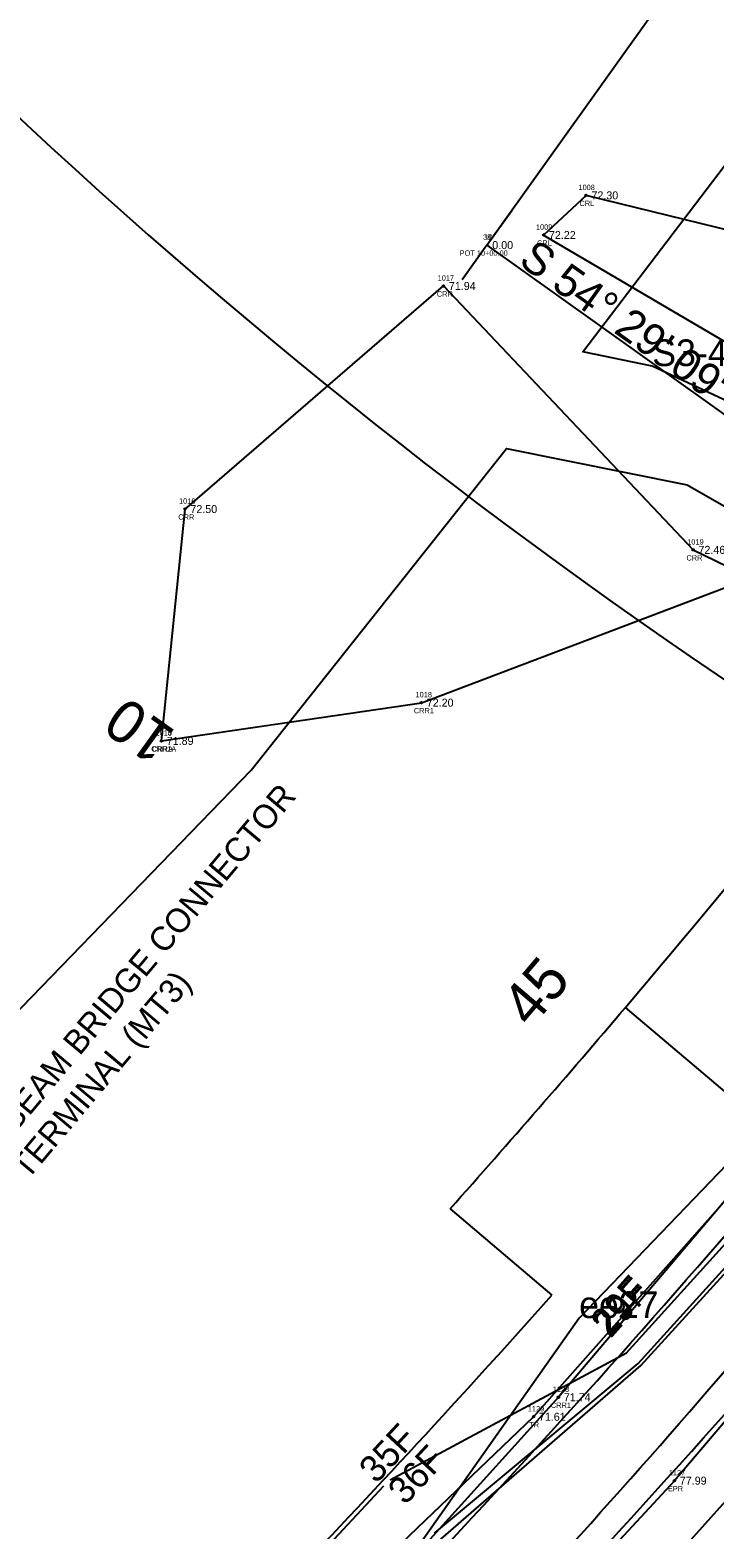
# Model space of a CAD drawing. Extents: x 2500794 to 2511032, y 910653 to 917533.
# Drawn here: x 2505570 to 2505698.2, y 913378 to 913659 of the extents above; entities that cross this region are included whole.
import ezdxf

# ---------------------------------------------------------------- set-up
doc = ezdxf.new("R2010")
doc.units = 0
for name, color, linetype in [('Default', 7, 'Continuous'), ('RD_EX_H2O', 7, 'Continuous'), ('RD_EX_H2O_txCode', 7, 'Continuous'), ('RD_EX_H2O_WetLd', 7, 'Continuous'), ('RD_EX_Road', 7, 'Continuous'), ('RD_EX_Road_txCode', 7, 'Continuous'), ('RD_EX_RW', 7, 'Continuous'), ('RD_EX_TX_H2O_ELEV', 7, 'Continuous'), ('RD_EX_TX_Road_ELEV', 7, 'Continuous'), ('RD_EX_TX_VEG_ELEV', 7, 'Continuous'), ('RD_EX_VEG', 7, 'Continuous'), ('RD_EX_VEG_txCode', 7, 'Continuous'), ('RD_EX_Wall', 7, 'Continuous'), ('RD_HC_Cl', 7, 'Continuous'), ('RD_HC_Data', 7, 'Continuous'), ('RD_HC_Data_Tic', 7, 'Continuous'), ('RD_HC_Survey_ELEV', 7, 'Continuous'), ('RD_HC_TX_Sta50', 7, 'Continuous'), ('RD_HC_txCode', 7, 'Continuous'), ('RD_PD_ALT1_TrvlWay', 7, 'Continuous'), ('RD_PD_CstnLmt', 7, 'Continuous'), ('RD_PD_CstnLmt_TX', 7, 'Continuous'), ('RD_PD_GR', 7, 'Continuous'), ('RD_PD_MedBWall', 7, 'Continuous'), ('RD_PD_RW', 7, 'Continuous'), ('RD_PD_Signals', 7, 'Continuous'), ('RD_SMD_Locator', 7, 'Continuous'), ('RD_XS_NPDES', 7, 'Continuous')]:
    doc.layers.add(name, color=color, linetype=linetype)

# ---------------------------------------------------------------- blocks, each defined once
blk = doc.blocks.new('POINT_DISPLAY')
at = {"layer": 'Default'}
blk.add_line((0, 0), (0, 0), dxfattribs=at)
blk = doc.blocks.new('Non-Wetland Waters (Tributaries)')
at = {"layer": 'Default'}
for points in [[(636472.197, 232037.165), (636470.066, 232041.194), (636461.608, 232045.336), (636444.397, 232053.387), (636441.101, 232054.059)], [(636437.461, 232049.468), (636446.058, 232047.739), (636453.797, 232043.307), (636460.346, 232037.221), (636461.867, 232032.723), (636463.078, 232025.417)]]:
    blk.add_lwpolyline(points, dxfattribs=at)
blk = doc.blocks.new('Wetlands')
at = {"layer": 'Default'}
for points in [[(636520.194, 232111.184), (636514.488, 232100.701), (636499.967, 232081.539), (636490.363, 232066.6), (636480.685, 232057.143), (636473.031, 232051.175), (636468.151, 232047.782), (636470.066, 232041.194), (636461.608, 232045.336), (636444.397, 232053.387), (636441.101, 232054.059), (636484.137, 232110.659), (636486.079, 232110.274), (636502.502, 232110.709), (636520.194, 232111.184)], [(636308.974, 231919.839), (636399.189, 232007.15), (636425.313, 232034.144), (636437.461, 232049.468), (636446.058, 232047.739), (636453.797, 232043.307), (636460.346, 232037.221), (636461.867, 232032.723), (636463.078, 232025.417), (636454.935, 232022.66), (636440.916, 232008.067), (636430.194, 231992.837)]]:
    blk.add_lwpolyline(points, dxfattribs=at)

msp = doc.modelspace()

# ---------------------------------------------------------------- linework, layer by layer
at = {"layer": 'RD_EX_H2O_txCode'}
for points in [[(2505762.26, 913658.11), (2505746.15, 913644.25), (2505726.47, 913615.21), (2505674.21, 913628.01), (2505666.25, 913620.58), (2505714.6, 913592.15), (2505793.9, 913560.45), (2505801.32, 913552.8), (2505803.7, 913539.77), (2505832.63, 913516.96), (2505848.42, 913517.19), (2505881.86, 913528.44), (2505910.2, 913538.78), (2505939.3, 913544.45), (2505946.25, 913542.54), (2505974.65, 913535.18), (2506004.11, 913524.7), (2506052.03, 913515.47), (2506115.49, 913494.68), (2506138.05, 913548.89)], [(2505594.65, 913525.76), (2505599.08, 913569.22), (2505647.5, 913611.03), (2505694.26, 913561.57), (2505732.63, 913542.98), (2505739.24, 913533.06)], [(2505594.65, 913525.76), (2505643.36, 913532.93), (2505701.94, 913555.13), (2505725.91, 913535.7), (2505739.24, 913533.06)], [(2505789.47, 913464.31), (2505758.18, 913486.1), (2505736.66, 913480.49), (2505719.32, 913463.86), (2505699.9, 913439.21), (2505669.03, 913402.75), (2505628.5, 913357.9), (2505593, 913316.39), (2505556.58, 913279.8), (2505487.72, 913211.38), (2505413.81, 913149.81), (2505341.31, 913072.1)]]:
    msp.add_lwpolyline(points, dxfattribs=at)
at = {"layer": 'RD_EX_Road'}
msp.add_lwpolyline([(2505758.23, 913470.96), (2505754.11, 913462.85), (2505725.4, 913427.85), (2505690.77, 913387.11), (2505650.25, 913343.36), (2505607.72, 913300.12), (2505570.97, 913264.99), (2505501.53, 913196.72), (2505431.76, 913128.83), (2505356.25, 913055.37)], dxfattribs=at)
at = {"layer": 'RD_EX_RW'}
msp.add_line((2505681.56, 913475.81), (2505713.58, 913448.63), dxfattribs=at)
for radius, start, end in [(2073.62, 319.67523, 322.60071), (2115.62, 314.20692, 319.67523), (2181.62, 314.20692, 319.67523)]:
    msp.add_arc((2504100.66, 914817.69), radius, start, end, dxfattribs=at)
at = {"layer": 'RD_EX_VEG'}
msp.add_lwpolyline([(2506002.64, 913815.25), (2505883.7, 913669.64), (2505827.83, 913593.29), (2505814.43, 913589.15), (2505792.49, 913560.55), (2505725.64, 913468.24), (2505664.37, 913399.09), (2505478.33, 913221), (2505411.99, 913152.19), (2505339.13, 913074.53)], dxfattribs=at)
at = {"layer": 'RD_EX_Wall'}
msp.add_arc((2506299.01, 914423.83), 1069.92, 219.1169, 240.15367, dxfattribs=at)
at = {"layer": 'RD_HC_Cl'}
msp.add_line((2505655.63, 913618.69), (2505757.7, 913545.85), dxfattribs=at)
msp.add_arc((2504100.66, 914817.69), 2148.62, 314.20692, 322.60071, dxfattribs=at)
at = {"layer": 'RD_HC_Data'}
msp.add_line((2505655.63, 913618.69), (2505726.55, 913718.06), dxfattribs=at)
at = {"layer": 'RD_HC_Data_Tic'}
for q in [(2505660.28, 913625.2), (2505650.98, 913612.18)]:
    msp.add_line((2505655.63, 913618.69), q, dxfattribs=at)
at = {"layer": 'RD_PD_ALT1_TrvlWay'}
for radius, end in [(2137.62, 319.99941), (2159.62, 320.00487)]:
    msp.add_arc((2504100.66, 914817.69), radius, 314.20692, end, dxfattribs=at)
at = {"layer": 'RD_PD_CstnLmt'}
for p, q in [((2505683.99, 913409.06), (2505717.08, 913445.66)), ((2505645.8, 913377.25), (2505683.99, 913409.06))]:
    msp.add_line(p, q, dxfattribs=at)
at = {"layer": 'RD_PD_GR'}
for centre, radius, start, end in [((2504614.7, 914336.04), 1428.32, 312.89707, 320.06268), ((2504296.24, 914635.52), 1898.71, 313.80927, 319.3112)]:
    msp.add_arc(centre, radius, start, end, dxfattribs=at)
at = {"layer": 'RD_PD_RW'}
msp.add_line((2505648.75, 913438.08), (2505667.81, 913421.9), dxfattribs=at)
for radius, start, end in [(2073.62, 318.29369, 319.67523), (2098.62, 314.20692, 318.31015), (2223.62, 314.20692, 319.67523)]:
    msp.add_arc((2504100.66, 914817.69), radius, start, end, dxfattribs=at)
at = {"layer": 'RD_PD_Signals'}
for p, q in [((2505684.44, 913408.67), (2505717.66, 913445.17)), ((2505646.99, 913376.15), (2505684.44, 913408.67))]:
    msp.add_line(p, q, dxfattribs=at)
at = {"layer": 'RD_SMD_Locator'}
for centre in [(2505674.21, 913628.01), (2505666.25, 913620.58), (2505647.5, 913611.03), (2505599.08, 913569.22), (2505694.26, 913561.57), (2505643.36, 913532.93), (2505594.65, 913525.76), (2505594.65, 913525.76), (2505669.03, 913402.75), (2505664.37, 913399.09), (2505690.77, 913387.11)]:
    msp.add_circle(centre, 0.15, dxfattribs=at)
at = {"layer": 'RD_XS_NPDES'}
for p, q in [((2505681.77, 913411.08), (2505714.85, 913447.67)), ((2505637.48, 913387.24), (2505681.77, 913411.08)), ((2505602.77, 913350.15), (2505636.29, 913386.12))]:
    msp.add_line(p, q, dxfattribs=at)

# ---------------------------------------------------------------- block references
at = {"layer": 'Default', "xscale": 3.937007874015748, "yscale": 3.937007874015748}
for name, p in [('Wetlands', (0, 0)), ('Non-Wetland Waters (Tributaries)', (0, 0)), ('POINT_DISPLAY', (2505686.6, 913596.01)), ('POINT_DISPLAY', (2505686.6, 913596.01)), ('POINT_DISPLAY', (2505672.9, 913417.59)), ('POINT_DISPLAY', (2505672.9, 913417.59))]:
    msp.add_blockref(name, p, dxfattribs=at)
at = {"layer": 'RD_EX_H2O', "xscale": 3.937007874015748, "yscale": 3.937007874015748}
msp.add_blockref('Non-Wetland Waters (Tributaries)', (0, 0), dxfattribs=at)
at = {"layer": 'RD_EX_H2O_WetLd', "xscale": 3.937007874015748, "yscale": 3.937007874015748}
msp.add_blockref('Wetlands', (0, 0), dxfattribs=at)

# ---------------------------------------------------------------- texts
at = {"layer": 'Default'}
for s, p in [('S3-4L', (2505686.6, 913596.01)), ('S3-4L', (2505686.6, 913596.01)), ('ee27', (2505672.9, 913417.59)), ('ee27', (2505672.9, 913417.59))]:
    msp.add_text(s, height=5, dxfattribs=at).set_placement(p)
at = {"layer": 'RD_EX_H2O_txCode'}
for s, p in [('1008', (2505672.78, 913629.01)), ('CRL', (2505672.98, 913626.01)), ('1009', (2505664.82, 913621.58)), ('CRL', (2505665.02, 913618.58)), ('1017', (2505646.4, 913612.03)), ('CRR', (2505646.25, 913609.03)), ('1016', (2505597.95, 913570.22)), ('CRR', (2505597.82, 913567.22)), ('1019', (2505693.16, 913562.57)), ('CRR', (2505693.01, 913559.57)), ('1018', (2505642.26, 913533.93)), ('CRR1', (2505641.94, 913530.93)), ('1014', (2505593.54, 913526.76)), ('1015', (2505593.54, 913526.76)), ('CRR1A', (2505592.74, 913523.76)), ('CRRA', (2505592.9, 913523.76)), ('1128', (2505667.97, 913403.75)), ('CRR1', (2505667.61, 913400.75))]:
    msp.add_text(s, height=1, dxfattribs=at).set_placement(p)
at = {"layer": 'RD_EX_Road_txCode'}
for s, p in [('1127', (2505689.71, 913388.11)), ('EPR', (2505689.54, 913385.11))]:
    msp.add_text(s, height=1, dxfattribs=at).set_placement(p)
at = {"layer": 'RD_EX_TX_H2O_ELEV'}
for s, p in [('72.30', (2505675.21, 913627.26)), ('72.22', (2505667.25, 913619.83)), ('71.94', (2505648.5, 913610.28)), ('72.50', (2505600.08, 913568.47)), ('72.46', (2505695.26, 913560.82)), ('72.20', (2505644.36, 913532.18)), ('71.89', (2505595.65, 913525.01)), ('71.89', (2505595.65, 913525.01)), ('71.74', (2505670.03, 913402))]:
    msp.add_text(s, height=1.5, dxfattribs=at).set_placement(p)
at = {"layer": 'RD_EX_TX_Road_ELEV'}
msp.add_text('77.99', height=1.5, dxfattribs=at).set_placement((2505691.77, 913386.36))
at = {"layer": 'RD_EX_TX_VEG_ELEV'}
msp.add_text('71.61', height=1.5, dxfattribs=at).set_placement((2505665.37, 913398.34))
at = {"layer": 'RD_EX_VEG_txCode'}
for s, p in [('1129', (2505663.3, 913400.09)), ('TR', (2505663.57, 913397.09))]:
    msp.add_text(s, height=1, dxfattribs=at).set_placement(p)
at = {"layer": 'RD_HC_Data'}
msp.add_text('S 54%%d 29\' 09" E', height=6, rotation=324.4859, dxfattribs=at).set_placement((2505661.32, 913615.19))
at = {"layer": 'RD_HC_Survey_ELEV'}
msp.add_text('0.00', height=1.5, dxfattribs=at).set_placement((2505656.63, 913617.94))
msp.add_text('0.00', height=1.5, dxfattribs=at).set_placement((2505656.63, 913617.94))
at = {"layer": 'RD_HC_TX_Sta50'}
for s, rotation, p in [('10', 144.4859, (2505597.61, 913527.41)), ('45', 49.6752, (2505663.89, 913471.73))]:
    msp.add_text(s, height=8, rotation=rotation, dxfattribs=at).set_placement(p)
at = {"layer": 'RD_HC_txCode'}
for s, p in [('38', (2505654.9, 913619.69)), ('10', (2505655.14, 913619.69)), ('POT 10+00.00', (2505650.52, 913616.69)), ('POT 10+00.00', (2505650.52, 913616.69))]:
    msp.add_text(s, height=1, dxfattribs=at).set_placement(p)
at = {"layer": 'RD_PD_CstnLmt_TX'}
for s, rotation, p in [('29F', 48.3419, (2505678.39, 913414.05)), ('36F', 47.0086, (2505640.31, 913382.37))]:
    msp.add_text(s, height=5, rotation=rotation, dxfattribs=at).set_placement(p)
at = {"layer": 'RD_PD_MedBWall'}
for s, p in [('CONSTRUCT THRIE BEAM BRIDGE CONNECTOR', (2505529.27, 913406.92)), ('CONSTRUCT END TERMINAL (MT3)', (2505535.02, 913402.1))]:
    msp.add_text(s, height=4.5, rotation=50.0195, dxfattribs=at).set_placement(p)
at = {"layer": 'RD_PD_Signals'}
for s, rotation, p in [('29F', 48.3419, (2505678.83, 913413.66)), ('35F', 47.0086, (2505634.89, 913386.38))]:
    msp.add_text(s, height=5, rotation=rotation, dxfattribs=at).set_placement(p)

doc.saveas('drawing.dxf')
